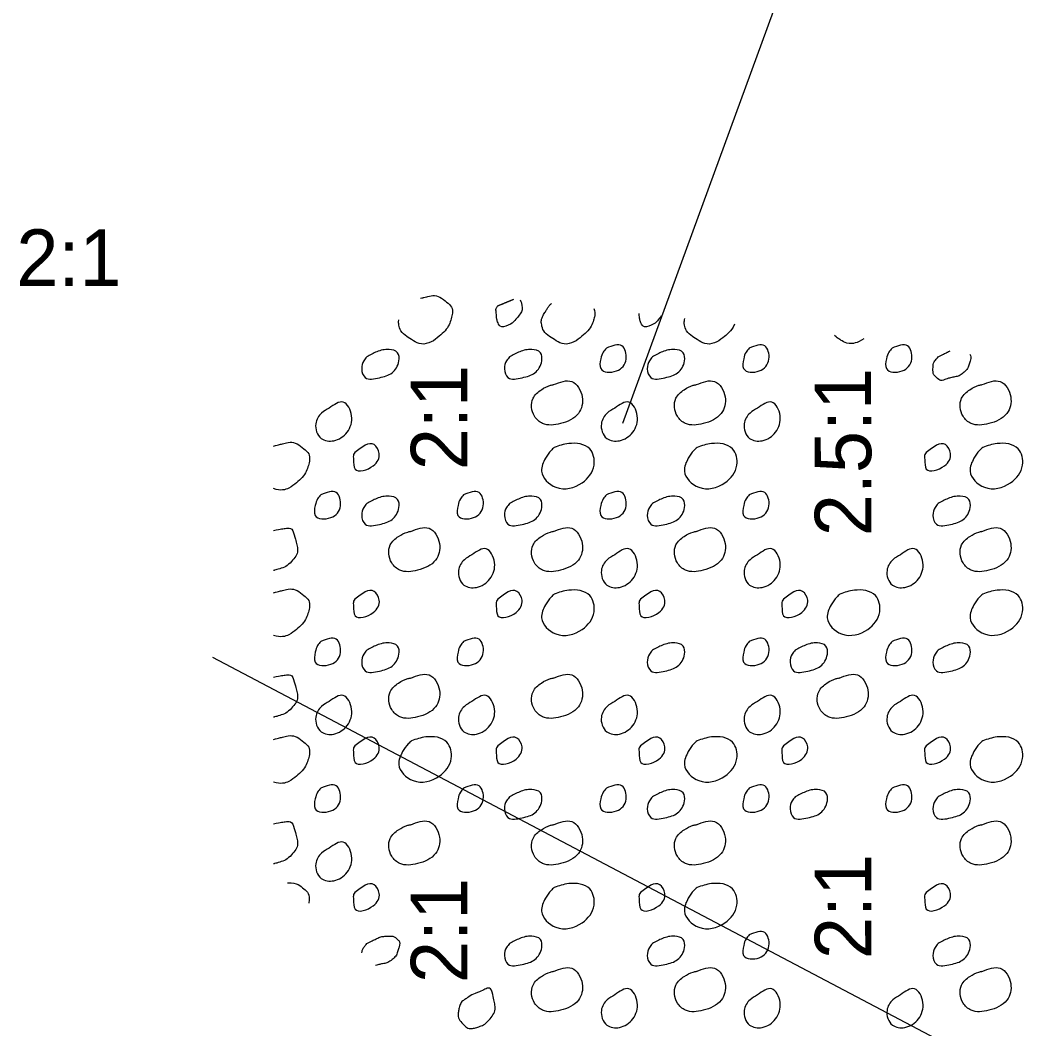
# Model space of a CAD drawing. Extents: x 0 to 486, y 0 to 220.
# Drawn here: x 125.73 to 150.63, y 140.54 to 165.5 of the extents above; entities that cross this region are included whole.
import ezdxf

# ---------------------------------------------------------------- set-up
doc = ezdxf.new("R2010")
doc.units = 0
doc.layers.add('GE_X_Alignment_100_Cardinal_Points', color=7, linetype='Continuous')
doc.layers.add('SV_X_Shot_Marker', color=7, linetype='Continuous')

msp = doc.modelspace()

# ---------------------------------------------------------------- linework, layer by layer
at = {"layer": 'GE_X_Alignment_100_Cardinal_Points'}
for p, q in [((140.646, 155.527), (147.075, 173.087)), ((176.497, 125.503), (130.5, 149.727))]:
    msp.add_line(p, q, dxfattribs=at)
at = {"layer": 'SV_X_Shot_Marker'}
for points, degree in [([(135.644, 158.621), (135.687, 158.633), (135.73, 158.644), (135.773, 158.655), (135.947, 158.7), (136.121, 158.668), (136.294, 158.523), (136.429, 158.411), (136.437, 158.245), (136.402, 158.121), (136.357, 157.964), (136.258, 157.816), (136.106, 157.686), (135.916, 157.524), (135.652, 157.46), (135.458, 157.575), (135.3, 157.668), (135.134, 157.808), (135.103, 157.973), (135.097, 158.009), (135.099, 158.046), (135.107, 158.084)], 3), ([(138.109, 158.579), (138.136, 158.528), (138.151, 158.453), (138.155, 158.41), (138.164, 158.31), (138.088, 158.206), (138.006, 158.107), (137.894, 157.973), (137.614, 157.876), (137.556, 158.023), (137.525, 158.102), (137.52, 158.182), (137.517, 158.263), (137.515, 158.303), (137.5, 158.348), (137.521, 158.384), (137.532, 158.402), (137.543, 158.418), (137.554, 158.436)], 3), ([(137.554, 158.436), (137.686, 158.489), (137.817, 158.545), (137.948, 158.597)], 2), ([(139.935, 158.372), (139.964, 158.287), (139.959, 158.196), (139.938, 158.121), (139.893, 157.964), (139.794, 157.816), (139.642, 157.686), (139.452, 157.524), (139.188, 157.46), (138.993, 157.575), (138.836, 157.668), (138.67, 157.808), (138.639, 157.973), (138.62, 158.076), (138.674, 158.196), (138.734, 158.292), (138.777, 158.36), (138.816, 158.429), (138.873, 158.484), (138.875, 158.487), (138.878, 158.489), (138.88, 158.491)], 3), ([(141.602, 158.184), (141.583, 158.158), (141.563, 158.133), (141.542, 158.107), (141.43, 157.973), (141.15, 157.876), (141.092, 158.023), (141.063, 158.096), (141.057, 158.171), (141.053, 158.246)], 3), ([(143.417, 157.979), (143.363, 157.874), (143.283, 157.776), (143.178, 157.686), (142.988, 157.524), (142.724, 157.46), (142.529, 157.575), (142.372, 157.668), (142.205, 157.808), (142.175, 157.973), (142.167, 158.019), (142.173, 158.069), (142.187, 158.118)], 3), ([(146.619, 157.617), (146.442, 157.508), (146.229, 157.478), (146.065, 157.575), (146.006, 157.61), (145.945, 157.652), (145.891, 157.699)], 3), ([(148.453, 157.172), (148.537, 157.214), (148.62, 157.255), (148.703, 157.297), (148.72, 157.305), (148.737, 157.312), (148.754, 157.318)], 3), ([(149.241, 157.241), (149.272, 157.186), (149.264, 157.123), (149.249, 157.07), (149.22, 156.965), (149.18, 156.858), (149.078, 156.774), (148.978, 156.69), (148.872, 156.679), (148.765, 156.654), (148.652, 156.627), (148.523, 156.561), (148.413, 156.659), (148.341, 156.725), (148.326, 156.801), (148.328, 156.875), (148.329, 156.942), (148.337, 157.02), (148.379, 157.075), (148.404, 157.108), (148.428, 157.14), (148.453, 157.172)], 3), ([(132, 154.962), (132.079, 154.983), (132.158, 155.004), (132.238, 155.024), (132.411, 155.069), (132.585, 155.038), (132.758, 154.893), (132.893, 154.78), (132.901, 154.614), (132.866, 154.49), (132.821, 154.334), (132.722, 154.185), (132.57, 154.055), (132.405, 153.914), (132.183, 153.847), (132, 153.909)], 3), ([(132, 152.877), (132.105, 152.895), (132.21, 152.913), (132.315, 152.928), (132.466, 152.949), (132.536, 152.69), (132.574, 152.548), (132.609, 152.419), (132.586, 152.262), (132.478, 152.141), (132.344, 151.994), (132.196, 151.937), (132.032, 151.889), (132.021, 151.886), (132.011, 151.883), (132, 151.88)], 3), ([(132, 151.332), (132.079, 151.353), (132.158, 151.373), (132.238, 151.394), (132.411, 151.439), (132.585, 151.407), (132.758, 151.262), (132.893, 151.15), (132.901, 150.984), (132.866, 150.86), (132.821, 150.703), (132.722, 150.555), (132.57, 150.425), (132.405, 150.283), (132.183, 150.217), (132, 150.278)], 3), ([(132, 149.246), (132.105, 149.265), (132.21, 149.283), (132.315, 149.298), (132.466, 149.319), (132.536, 149.059), (132.574, 148.918), (132.609, 148.789), (132.586, 148.631), (132.478, 148.511), (132.344, 148.363), (132.196, 148.307), (132.032, 148.258), (132.021, 148.255), (132.011, 148.252), (132, 148.25)], 3), ([(132, 147.701), (132.079, 147.722), (132.158, 147.743), (132.238, 147.763), (132.411, 147.808), (132.585, 147.777), (132.758, 147.632), (132.893, 147.52), (132.901, 147.353), (132.866, 147.229), (132.821, 147.073), (132.722, 146.924), (132.57, 146.794), (132.405, 146.653), (132.183, 146.586), (132, 146.648)], 3), ([(132, 145.616), (132.105, 145.634), (132.21, 145.653), (132.315, 145.667), (132.466, 145.688), (132.536, 145.429), (132.574, 145.287), (132.609, 145.158), (132.586, 145.001), (132.478, 144.881), (132.344, 144.733), (132.196, 144.676), (132.032, 144.628), (132.021, 144.625), (132.011, 144.622), (132, 144.619)], 3), ([(132.347, 144.151), (132.484, 144.159), (132.622, 144.116), (132.758, 144.001), (132.874, 143.904), (132.897, 143.768), (132.878, 143.652)], 3), ([(134.31, 142.65), (134.393, 142.692), (134.477, 142.733), (134.56, 142.775), (134.652, 142.821), (134.761, 142.83), (134.861, 142.833), (134.934, 142.835), (135.005, 142.817), (135.072, 142.752), (135.132, 142.692), (135.124, 142.612), (135.106, 142.548), (135.076, 142.443), (135.037, 142.337), (134.935, 142.252), (134.835, 142.169), (134.729, 142.157), (134.622, 142.132), (134.59, 142.124), (134.557, 142.114), (134.524, 142.105)], 3), ([(134.189, 142.42), (134.195, 142.468), (134.208, 142.516), (134.236, 142.553), (134.261, 142.586), (134.285, 142.618), (134.31, 142.65)], 3), ([(136.913, 141.378), (137.03, 141.429), (137.147, 141.479), (137.264, 141.529), (137.386, 141.581), (137.445, 141.315), (137.472, 141.191), (137.5, 141.06), (137.466, 140.913), (137.36, 140.786), (137.26, 140.666), (137.147, 140.61), (137.027, 140.573), (136.931, 140.544), (136.81, 140.54), (136.716, 140.633), (136.602, 140.745), (136.56, 140.877), (136.583, 140.992), (136.601, 141.083), (136.643, 141.203), (136.728, 141.259), (136.79, 141.3), (136.851, 141.338), (136.913, 141.378)], 3)]:
    msp.add_open_spline(points, degree=degree, dxfattribs=at)
for points in [[(134.31, 157.172), (134.56, 157.297), (134.861, 157.354), (135.072, 157.274), (135.106, 157.07), (134.935, 156.774), (134.622, 156.654), (134.27, 156.659), (134.184, 156.875), (134.236, 157.075), (134.31, 157.172)], [(137.846, 157.172), (138.096, 157.297), (138.397, 157.354), (138.608, 157.274), (138.642, 157.07), (138.471, 156.774), (138.158, 156.654), (137.806, 156.659), (137.72, 156.875), (137.772, 157.075), (137.846, 157.172)], [(140.244, 157.389), (140.626, 157.444), (140.73, 157.116), (140.49, 156.822), (140.103, 156.879), (140.106, 157.124), (140.164, 157.288), (140.244, 157.389)], [(141.382, 157.172), (141.632, 157.297), (141.933, 157.354), (142.143, 157.274), (142.178, 157.07), (142.007, 156.774), (141.693, 156.654), (141.342, 156.659), (141.256, 156.875), (141.308, 157.075), (141.382, 157.172)], [(143.78, 157.389), (144.162, 157.444), (144.266, 157.116), (144.026, 156.822), (143.639, 156.879), (143.642, 157.124), (143.7, 157.288), (143.78, 157.389)], [(147.316, 157.389), (147.698, 157.444), (147.802, 157.116), (147.562, 156.822), (147.175, 156.879), (147.178, 157.124), (147.236, 157.288), (147.316, 157.389)], [(138.933, 156.483), (139.387, 156.559), (139.646, 156.179), (139.549, 155.772), (139.103, 155.519), (138.663, 155.522), (138.464, 155.7), (138.428, 156.145), (138.633, 156.359), (138.858, 156.467), (138.941, 156.484)], [(142.468, 156.483), (142.923, 156.559), (143.182, 156.179), (143.085, 155.772), (142.639, 155.519), (142.199, 155.522), (142, 155.7), (141.963, 156.145), (142.168, 156.359), (142.394, 156.467), (142.477, 156.484)], [(149.54, 156.483), (149.994, 156.559), (150.253, 156.179), (150.157, 155.772), (149.711, 155.519), (149.271, 155.522), (149.072, 155.7), (149.035, 156.145), (149.24, 156.359), (149.466, 156.467), (149.548, 156.484)], [(133.377, 155.9), (133.728, 156.051), (133.936, 155.713), (133.824, 155.308), (133.491, 155.095), (133.18, 155.154), (133.047, 155.514), (133.193, 155.781), (133.377, 155.9)], [(140.448, 155.9), (140.8, 156.051), (141.008, 155.713), (140.896, 155.308), (140.563, 155.095), (140.252, 155.154), (140.118, 155.514), (140.264, 155.781), (140.448, 155.9)], [(143.984, 155.9), (144.336, 156.051), (144.543, 155.713), (144.432, 155.308), (144.098, 155.095), (143.788, 155.154), (143.654, 155.514), (143.8, 155.781), (143.984, 155.9)], [(134.018, 154.805), (134.493, 154.998), (134.619, 154.779), (134.47, 154.477), (134.02, 154.393), (133.981, 154.633), (133.985, 154.754), (134.018, 154.805)], [(138.953, 154.931), (139.309, 155.024), (139.83, 154.893), (139.938, 154.49), (139.642, 154.055), (138.993, 153.944), (138.639, 154.343), (138.734, 154.661), (138.873, 154.854), (138.953, 154.931)], [(142.489, 154.931), (142.845, 155.024), (143.366, 154.893), (143.473, 154.49), (143.178, 154.055), (142.529, 153.944), (142.175, 154.343), (142.27, 154.661), (142.408, 154.854), (142.489, 154.931)], [(148.162, 154.805), (148.637, 154.998), (148.763, 154.779), (148.613, 154.477), (148.163, 154.393), (148.124, 154.633), (148.128, 154.754), (148.162, 154.805)], [(149.561, 154.931), (149.917, 155.024), (150.438, 154.893), (150.545, 154.49), (150.249, 154.055), (149.601, 153.944), (149.247, 154.343), (149.342, 154.661), (149.48, 154.854), (149.561, 154.931)], [(133.173, 153.758), (133.554, 153.814), (133.658, 153.486), (133.418, 153.191), (133.032, 153.248), (133.034, 153.494), (133.093, 153.657), (133.173, 153.758)], [(136.708, 153.758), (137.09, 153.814), (137.194, 153.486), (136.954, 153.191), (136.568, 153.248), (136.57, 153.494), (136.628, 153.657), (136.708, 153.758)], [(140.244, 153.758), (140.626, 153.814), (140.73, 153.486), (140.49, 153.191), (140.103, 153.248), (140.106, 153.494), (140.164, 153.657), (140.244, 153.758)], [(143.78, 153.758), (144.162, 153.814), (144.266, 153.486), (144.026, 153.191), (143.639, 153.248), (143.642, 153.494), (143.7, 153.657), (143.78, 153.758)], [(134.31, 153.541), (134.56, 153.666), (134.861, 153.724), (135.072, 153.643), (135.106, 153.44), (134.935, 153.143), (134.622, 153.023), (134.27, 153.029), (134.184, 153.245), (134.236, 153.445), (134.31, 153.541)], [(137.846, 153.541), (138.096, 153.666), (138.397, 153.724), (138.608, 153.643), (138.642, 153.44), (138.471, 153.143), (138.158, 153.023), (137.806, 153.029), (137.72, 153.245), (137.772, 153.445), (137.846, 153.541)], [(141.382, 153.541), (141.632, 153.666), (141.933, 153.724), (142.143, 153.643), (142.178, 153.44), (142.007, 153.143), (141.693, 153.023), (141.342, 153.029), (141.256, 153.245), (141.308, 153.445), (141.382, 153.541)], [(148.453, 153.541), (148.703, 153.666), (149.004, 153.724), (149.215, 153.643), (149.249, 153.44), (149.078, 153.143), (148.765, 153.023), (148.413, 153.029), (148.328, 153.245), (148.379, 153.445), (148.453, 153.541)], [(135.397, 152.852), (135.851, 152.928), (136.11, 152.548), (136.013, 152.141), (135.568, 151.889), (135.128, 151.891), (134.928, 152.07), (134.892, 152.515), (135.097, 152.728), (135.323, 152.836), (135.405, 152.854)], [(138.933, 152.852), (139.387, 152.928), (139.646, 152.548), (139.549, 152.141), (139.103, 151.889), (138.663, 151.891), (138.464, 152.07), (138.428, 152.515), (138.633, 152.728), (138.858, 152.836), (138.941, 152.854)], [(142.468, 152.852), (142.923, 152.928), (143.182, 152.548), (143.085, 152.141), (142.639, 151.889), (142.199, 151.891), (142, 152.07), (141.963, 152.515), (142.168, 152.728), (142.394, 152.836), (142.477, 152.854)], [(149.54, 152.852), (149.994, 152.928), (150.253, 152.548), (150.157, 152.141), (149.711, 151.889), (149.271, 151.891), (149.072, 152.07), (149.035, 152.515), (149.24, 152.728), (149.466, 152.836), (149.548, 152.854)], [(136.913, 152.27), (137.264, 152.421), (137.472, 152.082), (137.36, 151.677), (137.027, 151.465), (136.716, 151.524), (136.583, 151.883), (136.728, 152.151), (136.913, 152.27)], [(140.448, 152.27), (140.8, 152.421), (141.008, 152.082), (140.896, 151.677), (140.563, 151.465), (140.252, 151.524), (140.118, 151.883), (140.264, 152.151), (140.448, 152.27)], [(143.984, 152.27), (144.336, 152.421), (144.543, 152.082), (144.432, 151.677), (144.098, 151.465), (143.788, 151.524), (143.654, 151.883), (143.8, 152.151), (143.984, 152.27)], [(147.52, 152.27), (147.872, 152.421), (148.079, 152.082), (147.968, 151.677), (147.634, 151.465), (147.323, 151.524), (147.19, 151.883), (147.336, 152.151), (147.52, 152.27)], [(134.018, 151.175), (134.493, 151.367), (134.619, 151.149), (134.47, 150.846), (134.02, 150.762), (133.981, 151.002), (133.985, 151.123), (134.018, 151.175)], [(137.554, 151.175), (138.029, 151.367), (138.155, 151.149), (138.006, 150.846), (137.556, 150.762), (137.517, 151.002), (137.521, 151.123), (137.554, 151.175)], [(138.953, 151.301), (139.309, 151.394), (139.83, 151.262), (139.938, 150.86), (139.642, 150.425), (138.993, 150.314), (138.639, 150.712), (138.734, 151.031), (138.873, 151.223), (138.953, 151.301)], [(141.09, 151.175), (141.565, 151.367), (141.691, 151.149), (141.542, 150.846), (141.092, 150.762), (141.053, 151.002), (141.057, 151.123), (141.09, 151.175)], [(144.626, 151.175), (145.101, 151.367), (145.227, 151.149), (145.078, 150.846), (144.628, 150.762), (144.588, 151.002), (144.593, 151.123), (144.626, 151.175)], [(146.025, 151.301), (146.381, 151.394), (146.902, 151.262), (147.009, 150.86), (146.713, 150.425), (146.065, 150.314), (145.711, 150.712), (145.806, 151.031), (145.944, 151.223), (146.025, 151.301)], [(149.561, 151.301), (149.917, 151.394), (150.438, 151.262), (150.545, 150.86), (150.249, 150.425), (149.601, 150.314), (149.247, 150.712), (149.342, 151.031), (149.48, 151.223), (149.561, 151.301)], [(133.173, 150.128), (133.554, 150.183), (133.658, 149.855), (133.418, 149.561), (133.032, 149.618), (133.034, 149.863), (133.093, 150.027), (133.173, 150.128)], [(134.31, 149.911), (134.56, 150.036), (134.861, 150.093), (135.072, 150.013), (135.106, 149.809), (134.935, 149.513), (134.622, 149.393), (134.27, 149.398), (134.184, 149.614), (134.236, 149.814), (134.31, 149.911)], [(136.708, 150.128), (137.09, 150.183), (137.194, 149.855), (136.954, 149.561), (136.568, 149.618), (136.57, 149.863), (136.628, 150.027), (136.708, 150.128)], [(141.382, 149.911), (141.632, 150.036), (141.933, 150.093), (142.143, 150.013), (142.178, 149.809), (142.007, 149.513), (141.693, 149.393), (141.342, 149.398), (141.256, 149.614), (141.308, 149.814), (141.382, 149.911)], [(143.78, 150.128), (144.162, 150.183), (144.266, 149.855), (144.026, 149.561), (143.639, 149.618), (143.642, 149.863), (143.7, 150.027), (143.78, 150.128)], [(144.918, 149.911), (145.168, 150.036), (145.468, 150.093), (145.679, 150.013), (145.713, 149.809), (145.543, 149.513), (145.229, 149.393), (144.878, 149.398), (144.792, 149.614), (144.843, 149.814), (144.918, 149.911)], [(147.316, 150.128), (147.698, 150.183), (147.802, 149.855), (147.562, 149.561), (147.175, 149.618), (147.178, 149.863), (147.236, 150.027), (147.316, 150.128)], [(148.453, 149.911), (148.703, 150.036), (149.004, 150.093), (149.215, 150.013), (149.249, 149.809), (149.078, 149.513), (148.765, 149.393), (148.413, 149.398), (148.328, 149.614), (148.379, 149.814), (148.453, 149.911)], [(135.397, 149.222), (135.851, 149.298), (136.11, 148.918), (136.013, 148.511), (135.568, 148.258), (135.128, 148.261), (134.928, 148.439), (134.892, 148.884), (135.097, 149.098), (135.323, 149.206), (135.405, 149.223)], [(138.933, 149.222), (139.387, 149.298), (139.646, 148.918), (139.549, 148.511), (139.103, 148.258), (138.663, 148.261), (138.464, 148.439), (138.428, 148.884), (138.633, 149.098), (138.858, 149.206), (138.941, 149.223)], [(146.004, 149.222), (146.458, 149.298), (146.718, 148.918), (146.621, 148.511), (146.175, 148.258), (145.735, 148.261), (145.536, 148.439), (145.499, 148.884), (145.704, 149.098), (145.93, 149.206), (146.013, 149.223)], [(133.377, 148.639), (133.728, 148.79), (133.936, 148.452), (133.824, 148.047), (133.491, 147.834), (133.18, 147.893), (133.047, 148.253), (133.193, 148.52), (133.377, 148.639)], [(136.913, 148.639), (137.264, 148.79), (137.472, 148.452), (137.36, 148.047), (137.027, 147.834), (136.716, 147.893), (136.583, 148.253), (136.728, 148.52), (136.913, 148.639)], [(140.448, 148.639), (140.8, 148.79), (141.008, 148.452), (140.896, 148.047), (140.563, 147.834), (140.252, 147.893), (140.118, 148.253), (140.264, 148.52), (140.448, 148.639)], [(143.984, 148.639), (144.336, 148.79), (144.543, 148.452), (144.432, 148.047), (144.098, 147.834), (143.788, 147.893), (143.654, 148.253), (143.8, 148.52), (143.984, 148.639)], [(147.52, 148.639), (147.872, 148.79), (148.079, 148.452), (147.968, 148.047), (147.634, 147.834), (147.323, 147.893), (147.19, 148.253), (147.336, 148.52), (147.52, 148.639)], [(134.018, 147.544), (134.493, 147.737), (134.619, 147.518), (134.47, 147.216), (134.02, 147.132), (133.981, 147.372), (133.985, 147.493), (134.018, 147.544)], [(137.554, 147.544), (138.029, 147.737), (138.155, 147.518), (138.006, 147.216), (137.556, 147.132), (137.517, 147.372), (137.521, 147.493), (137.554, 147.544)], [(141.09, 147.544), (141.565, 147.737), (141.691, 147.518), (141.542, 147.216), (141.092, 147.132), (141.053, 147.372), (141.057, 147.493), (141.09, 147.544)], [(144.626, 147.544), (145.101, 147.737), (145.227, 147.518), (145.078, 147.216), (144.628, 147.132), (144.588, 147.372), (144.593, 147.493), (144.626, 147.544)], [(148.162, 147.544), (148.637, 147.737), (148.763, 147.518), (148.613, 147.216), (148.163, 147.132), (148.124, 147.372), (148.128, 147.493), (148.162, 147.544)], [(135.418, 147.67), (135.773, 147.763), (136.294, 147.632), (136.402, 147.229), (136.106, 146.794), (135.458, 146.683), (135.103, 147.082), (135.198, 147.4), (135.337, 147.593), (135.418, 147.67)], [(142.489, 147.67), (142.845, 147.763), (143.366, 147.632), (143.473, 147.229), (143.178, 146.794), (142.529, 146.683), (142.175, 147.082), (142.27, 147.4), (142.408, 147.593), (142.489, 147.67)], [(149.561, 147.67), (149.917, 147.763), (150.438, 147.632), (150.545, 147.229), (150.249, 146.794), (149.601, 146.683), (149.247, 147.082), (149.342, 147.4), (149.48, 147.593), (149.561, 147.67)], [(133.173, 146.497), (133.554, 146.553), (133.658, 146.225), (133.418, 145.931), (133.032, 145.987), (133.034, 146.233), (133.093, 146.396), (133.173, 146.497)], [(136.708, 146.497), (137.09, 146.553), (137.194, 146.225), (136.954, 145.931), (136.568, 145.987), (136.57, 146.233), (136.628, 146.396), (136.708, 146.497)], [(140.244, 146.497), (140.626, 146.553), (140.73, 146.225), (140.49, 145.931), (140.103, 145.987), (140.106, 146.233), (140.164, 146.396), (140.244, 146.497)], [(143.78, 146.497), (144.162, 146.553), (144.266, 146.225), (144.026, 145.931), (143.639, 145.987), (143.642, 146.233), (143.7, 146.396), (143.78, 146.497)], [(147.316, 146.497), (147.698, 146.553), (147.802, 146.225), (147.562, 145.931), (147.175, 145.987), (147.178, 146.233), (147.236, 146.396), (147.316, 146.497)], [(137.846, 146.281), (138.096, 146.406), (138.397, 146.463), (138.608, 146.382), (138.642, 146.179), (138.471, 145.882), (138.158, 145.762), (137.806, 145.768), (137.72, 145.984), (137.772, 146.184), (137.846, 146.281)], [(141.382, 146.281), (141.632, 146.406), (141.933, 146.463), (142.143, 146.382), (142.178, 146.179), (142.007, 145.882), (141.693, 145.762), (141.342, 145.768), (141.256, 145.984), (141.308, 146.184), (141.382, 146.281)], [(144.918, 146.281), (145.168, 146.406), (145.468, 146.463), (145.679, 146.382), (145.713, 146.179), (145.543, 145.882), (145.229, 145.762), (144.878, 145.768), (144.792, 145.984), (144.843, 146.184), (144.918, 146.281)], [(148.453, 146.281), (148.703, 146.406), (149.004, 146.463), (149.215, 146.382), (149.249, 146.179), (149.078, 145.882), (148.765, 145.762), (148.413, 145.768), (148.328, 145.984), (148.379, 146.184), (148.453, 146.281)], [(135.397, 145.591), (135.851, 145.667), (136.11, 145.287), (136.013, 144.881), (135.568, 144.628), (135.128, 144.631), (134.928, 144.809), (134.892, 145.254), (135.097, 145.467), (135.323, 145.576), (135.405, 145.593)], [(138.933, 145.591), (139.387, 145.667), (139.646, 145.287), (139.549, 144.881), (139.103, 144.628), (138.663, 144.631), (138.464, 144.809), (138.428, 145.254), (138.633, 145.467), (138.858, 145.576), (138.941, 145.593)], [(142.468, 145.591), (142.923, 145.667), (143.182, 145.287), (143.085, 144.881), (142.639, 144.628), (142.199, 144.631), (142, 144.809), (141.963, 145.254), (142.168, 145.467), (142.394, 145.576), (142.477, 145.593)], [(149.54, 145.591), (149.994, 145.667), (150.253, 145.287), (150.157, 144.881), (149.711, 144.628), (149.271, 144.631), (149.072, 144.809), (149.035, 145.254), (149.24, 145.467), (149.466, 145.576), (149.548, 145.593)], [(133.377, 145.009), (133.728, 145.16), (133.936, 144.821), (133.824, 144.416), (133.491, 144.204), (133.18, 144.263), (133.047, 144.622), (133.193, 144.89), (133.377, 145.009)], [(134.018, 143.914), (134.493, 144.106), (134.619, 143.888), (134.47, 143.586), (134.02, 143.501), (133.981, 143.741), (133.985, 143.862), (134.018, 143.914)], [(138.953, 144.04), (139.309, 144.133), (139.83, 144.001), (139.938, 143.599), (139.642, 143.164), (138.993, 143.053), (138.639, 143.451), (138.734, 143.77), (138.873, 143.962), (138.953, 144.04)], [(141.09, 143.914), (141.565, 144.106), (141.691, 143.888), (141.542, 143.586), (141.092, 143.501), (141.053, 143.741), (141.057, 143.862), (141.09, 143.914)], [(142.489, 144.04), (142.845, 144.133), (143.366, 144.001), (143.473, 143.599), (143.178, 143.164), (142.529, 143.053), (142.175, 143.451), (142.27, 143.77), (142.408, 143.962), (142.489, 144.04)], [(148.162, 143.914), (148.637, 144.106), (148.763, 143.888), (148.613, 143.586), (148.163, 143.501), (148.124, 143.741), (148.128, 143.862), (148.162, 143.914)], [(137.846, 142.65), (138.096, 142.775), (138.397, 142.833), (138.608, 142.752), (138.642, 142.548), (138.471, 142.252), (138.158, 142.132), (137.806, 142.138), (137.72, 142.353), (137.772, 142.553), (137.846, 142.65)], [(141.382, 142.65), (141.632, 142.775), (141.933, 142.833), (142.143, 142.752), (142.178, 142.548), (142.007, 142.252), (141.693, 142.132), (141.342, 142.138), (141.256, 142.353), (141.308, 142.553), (141.382, 142.65)], [(143.78, 142.867), (144.162, 142.923), (144.266, 142.594), (144.026, 142.3), (143.639, 142.357), (143.642, 142.603), (143.7, 142.766), (143.78, 142.867)], [(148.453, 142.65), (148.703, 142.775), (149.004, 142.833), (149.215, 142.752), (149.249, 142.548), (149.078, 142.252), (148.765, 142.132), (148.413, 142.138), (148.328, 142.353), (148.379, 142.553), (148.453, 142.65)], [(138.933, 141.961), (139.387, 142.037), (139.646, 141.657), (139.549, 141.25), (139.103, 140.998), (138.663, 141), (138.464, 141.178), (138.428, 141.623), (138.633, 141.837), (138.858, 141.945), (138.941, 141.963)], [(142.468, 141.961), (142.923, 142.037), (143.182, 141.657), (143.085, 141.25), (142.639, 140.998), (142.199, 141), (142, 141.178), (141.963, 141.623), (142.168, 141.837), (142.394, 141.945), (142.477, 141.963)], [(149.54, 141.961), (149.994, 142.037), (150.253, 141.657), (150.157, 141.25), (149.711, 140.998), (149.271, 141), (149.072, 141.178), (149.035, 141.623), (149.24, 141.837), (149.466, 141.945), (149.548, 141.963)], [(140.448, 141.378), (140.8, 141.529), (141.008, 141.191), (140.896, 140.786), (140.563, 140.573), (140.252, 140.633), (140.118, 140.992), (140.264, 141.259), (140.448, 141.378)], [(143.984, 141.378), (144.336, 141.529), (144.543, 141.191), (144.432, 140.786), (144.098, 140.573), (143.788, 140.633), (143.654, 140.992), (143.8, 141.259), (143.984, 141.378)], [(147.52, 141.378), (147.872, 141.529), (148.079, 141.191), (147.968, 140.786), (147.634, 140.573), (147.323, 140.633), (147.19, 140.992), (147.336, 141.259), (147.52, 141.378)]]:
    msp.add_spline(points, degree=3, dxfattribs=at)

# ---------------------------------------------------------------- texts
at = {"layer": 'GE_X_Alignment_100_Cardinal_Points'}
for s, rotation, p in [('2:1', 0, (125.635, 158.927)), ('2:1', 90.0983, (136.802, 154.368)), ('2.5:1', 90.0983, (146.803, 152.734)), ('2:1', 90.0983, (146.802, 142.267)), ('2:1', 90.0983, (136.802, 141.674))]:
    msp.add_text(s, height=1.4, rotation=rotation, dxfattribs=at).set_placement(p)

doc.saveas('drawing.dxf')
